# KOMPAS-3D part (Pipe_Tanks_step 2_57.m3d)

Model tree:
1. X Axis
2. Y Axis
3. Z Axis  (labels: Pipe Dn 50; Valve Dy 50)
     Òîëùèíà ñòåíêè 1 = 1

Referenced files in C:\Documents and Settings\kashirsky\Мои документы\Camtasia Studio\Pipelines3D\Tanks\: Tanks_step 2.a3d
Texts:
  Pipe Dn 50
  Steel ASTM A295
  Three Point Plane
  Plane at Angle
  Line and Point Plane
  Axis through Two Vertices
  Axis of Feature
  Axis of Conical Surface
  Axis through Edge
  Trim by Surface
  Trim by Sketch
  Feature with No History
  Intersection Axis of Two Planes
  Two Line Plane
  Line and Face Plane
  Bend by line
  Hole in sheet body
  Cut in sheet body
  Point in CM
  Linear Dimension from Line to Point
  Surface Finish Symbol
  Geometric Tolerance Symbol
  Leader #1
  Leader #2
  Leader #3
  Shape Deviations and Datum
  Node point number
  Mark of coordination axis
  Node point designation
  Mark/Reference designation with leader
  Mark/reference designation on line
  Mark/Reference designation without leader
  Valve Dy 50
  Plane of section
